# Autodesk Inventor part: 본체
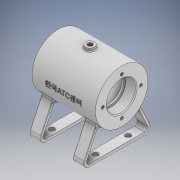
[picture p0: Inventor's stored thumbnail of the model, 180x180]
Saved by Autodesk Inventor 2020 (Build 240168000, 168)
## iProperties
Created: 2021-12
Part Number: 본체
Material: 일반
Document SubType Name: Modeling
Designer: Windows7
Density: 1 g/cm^3
Appearance: 기본값
Mass: 114.909 g
Surface Area: 355.108 cm^2
Volume: 114.909 cm^3
Author: Windows7
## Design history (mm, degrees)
sketch "스케치1"
  geometry: L1 (-35, 29)-(35, 29); L2 (35, 29)-(35, 0); L3 (35, 0)-(-35, 0); L4 (-35, 0)-(-35, 29); L5 (-35, 16)-(-23, 16); L6 (-23, 16)-(-23, 14); L7 (-23, 14)-(-21, 14); L8 (-21, 14)-(-21, 21); L9 (-21, 21)-(21, 21); L10 (21, 21)-(21, 16); L11 (23, 16)-(23, 16); L12 (23, 16)-(35, 16); L13 (21, 16)-(21, 14); L14 (21, 14)-(23, 14); L15 (23, 14)-(23, 16); 2 further points
  constraints: 30 end point, 10 perpendicular, 4 point on line, 2 collinear, 2 midpoint, 2 parallel, 1 horizontal, 1 vertical, 1 vertical alignment
  dimensions: "d0" = 58 diameter of L1 L3; "d1" = 70 distance of L1.start L1.end; "d2" = 12 distance of L5.start L5.end; "d3" = 12 distance of L11.end L12.end; "d4" = 42 distance of L8.end L9.end; "d5" = 32 diameter of L5 L3; "d6" = 28 diameter of L6.end L3; "d7" = 42 diameter of L9 L3; "d8" = 32 diameter of L12 L3
revolve "회전1" sketch "스케치1" stored, may be unused: angle "d9" = 90 deg
node "작업 평면1"
sketch "스케치2"
  geometry: L1 (-22.743, -17.993)-(-40, -55); L2 (-40, -55)-(0, -55); L3 (0, -55)-(0, -29); L4 (-20.574, -20.438)-(-35.291, -52); L5 (-35.291, -52)-(0, -52); L6 (0, -55)-(0, -52); C1 r 16 at (0, 0) reference; A1 r 29 centre (0, 0) between (-22.743, -17.993) and (0, -29) reference; 1 further point
  constraints: 12 end point, 3 point on circle, 1 collinear, 1 horizontal, 1 perpendicular, 1 point on line, 1 vertical alignment
  dimensions: "d11" = 65 deg angle of L2 L1; "d12" = 3 distance between parallel lines of L1 L4; "d14" = 3 distance between parallel lines of L2 L5; "d15" = 40 distance of L1.end L2.end; "d16" = 55 distance from line of L2 point (0, 0)
extrude "돌출1" join sketch "스케치2" distance "d17" = 12; taper "d18" = 0 deg
fillet "모깎기1" dims "d19" = 6
node "작업 평면2"
sketch "스케치3"
  geometry: C1 r 5 at (0, 0); 1 further point
  constraints: 1 centre point, 1 coincident
  dimensions: "d21" = 10 diameter of C1
extrude "돌출2" join sketch "스케치3" stored distance "d22" = 12; taper "d23" = 0 deg
sketch "스케치5"
  geometry: C1 r 5 at (0, 0) reference; C2 r 5 at (0, 0); 2 further points
  constraints: 2 coincident, 1 centre point
  dimensions: "d70" = 10 diameter of C2
hole "구멍1" sketch "스케치5" at (0, 0) diameter "d24" = 5.1881; stored, may be unused: countersink angle "d28" = 90 deg, drill point angle "d30" = 118 deg; dims "d25" = 6, "d26" = 6, "d27" = 6, "d29" = 8
node "작업 평면3"
sketch "스케치6"
  geometry: L1 (-20.739, 3.002)-(20.739, 3.002); L2 (20.739, 3.002)-(20.739, -3.002); L3 (20.739, -3.002)-(-20.739, -3.002); L4 (-20.739, -3.002)-(-20.739, 3.002); L5 (20.739, -3.002)-(-20.739, 3.002); L6 (20.739, 3.002)-(-20.739, -3.002); L7 (-35, -29)-(-35, 29) reference; L8 (-35, 29)-(35, 29) reference; 2 further points
  constraints: 4 end point, 1 midpoint, 2 other
  dimensions: "d32" = 35 distance from line of L7 point (0, 0); "d33" = 29 distance from line of point (0, 0) L8
feature "엠보싱1" sketch "스케치6" dims "d0" = 58, "d1" = 70, "d2" = 12, "d3" = 12, "d4" = 42, "d5" = 32, "d6" = 28, "d7" = 42, "d8" = 32, "d11" = 65 deg, "d12" = 3, "d14" = 3, "d15" = 40, "d16" = 55, "d34" = 0.5, "d35" = 0
sketch "스케치7"
  geometry: L1 (-42, 17.291)-(6, 17.291); L2 (6, 17.291)-(6, 53.291); L3 (6, 53.291)-(-42, 53.291); L4 (-42, 53.291)-(-42, 17.291); L5 (-48, 4.709)-(-48, 65.873) reference; 6 further points
  constraints: 8 end point, 4 coincident, 2 parallel, 1 horizontal, 1 horizontal alignment, 1 midpoint, 1 perpendicular
  dimensions: "d36" = 48 distance of L2.end L3.end; "d37" = 6 distance between parallel lines of L5 L4; "d38" = 36 distance between parallel lines of L1 L3
hole "구멍2" sketch "스케치7" at (-42, 53.291), (6, 53.291), (6, 17.291), (-42, 17.291) diameter "d39" = 6; stored, may be unused: countersink angle "d43" = 90 deg, drill point angle "d45" = 0 deg; dims "d40" = 8, "d41" = 6, "d42" = 6, "d44" = 8.8
sketch "스케치8" dims "d46" = 42
  geometry: L1 (0, 0)-(0, 43.275); 2 further points
  constraints: 2 end point, 1 coincident, 1 point on line, 1 vertical, 1 vertical alignment, 2 other
hole "구멍3" sketch "스케치8" at (0, 21) diameter "d47" = 3.242; stored, may be unused: countersink angle "d51" = 90 deg, drill point angle "d53" = 118 deg; dims "d48" = 8, "d49" = 6, "d50" = 6, "d52" = 10
sketch "스케치9"
  geometry: L1 (0, 0)-(-43.535, 0); L2 (0, 0)-(-30.07, -10.945)
  constraints: 4 end point, 1 horizontal
  dimensions: "d57" = 32 distance of L1.start L2.end; "d58" = 20 deg angle of L2 L1
node "작업 평면4"
sketch "스케치10"
  geometry: C1 r 6 at (0, 0); 2 further points
  constraints: 1 centre point, 1 coincident
  dimensions: "d59" = 12 diameter of C1
extrude "돌출3" join sketch "스케치10" stored distance "d60" = 12; taper "d61" = 0 deg
sketch "스케치11"
  geometry: C1 r 6 at (0, 0) reference; 2 further points
  constraints: 1 coincident
hole "구멍4" sketch "스케치11" at (0, 0) diameter "d62" = 5.1881; stored, may be unused: countersink angle "d66" = 90 deg, drill point angle "d68" = 0 deg; dims "d63" = 12, "d64" = 6, "d65" = 6, "d67" = 16
fillet "모깎기2" dims "d69" = 1
fillet "모깎기3" dims "d71" = 0.3
chamfer "모따기1" distance "d72" = 1; stored, may be unused: second distance "d73" = 2, angle "d74" = 45 deg
fillet "모깎기4" dims "d75" = 3
fillet "모깎기5" dims "d76" = 3
fillet "모깎기6" dims "d77" = 0.5
fillet "모깎기7" dims "d78" = 3
sketch "스케치13"
  geometry: L1 (18, -54.5)-(18, -52.5) reference; L2 (18.5, -52)-(29.5, -52) reference; L3 (30, -52.5)-(30, -54.5) reference; L4 (29.5, -55)-(18.5, -55) reference; L5 (-30, -54.5)-(-30, -52.5) reference; L6 (-29.5, -52)-(-18.5, -52) reference; L7 (-18, -52.5)-(-18, -54.5) reference; L8 (-18.5, -55)-(-29.5, -55) reference; L9 (24.026, -21)-(25, -22.621) reference; L10 (25, -22.621)-(35, -22.621) reference; L11 (35, -22.621)-(35, -29) reference; L12 (35, -29)-(-35, -29) reference; L13 (-35, -29)-(-35, -22.621) reference; L14 (-35, -22.621)-(-25, -22.621) reference; L15 (-25, -22.621)-(-24.026, -21) reference; L16 (-24.026, -21)-(-25, -19.379) reference; L17 (-25, -19.379)-(-35, -19.379) reference; L18 (-35, -19.379)-(-35, -17) reference; L19 (-35, -17)-(-34, -16) reference; L20 (-34, -16)-(-23.3, -16) reference; L21 (-23, -15.7)-(-23, -14) reference; L22 (-23, -14)-(-21, -14) reference; L23 (-21, -14)-(-21, -18) reference; L24 (-18, -21)-(18, -21) reference; L25 (21, -18)-(21, -14) reference; L26 (21, -14)-(23, -14) reference; L27 (23, -14)-(23, -15.7) reference; L28 (23.3, -16)-(34, -16) reference; L29 (34, -16)-(35, -17) reference; L30 (35, -17)-(35, -19.379) reference; L31 (35, -19.379)-(25, -19.379) reference; L32 (25, -19.379)-(24.026, -21) reference; L33 (25, 22.621)-(24.026, 21) reference; L34 (24.026, 21)-(25, 19.379) reference; L35 (25, 19.379)-(35, 19.379) reference; L36 (35, 19.379)-(35, 17) reference; L37 (35, 17)-(34, 16) reference; L38 (34, 16)-(23.3, 16) reference; L39 (23, 15.7)-(23, 14) reference; L40 (23, 14)-(21, 14) reference; L41 (21, 14)-(21, 18) reference; L42 (18, 21)-(-18, 21) reference; L43 (-21, 18)-(-21, 14) reference; L44 (-21, 14)-(-23, 14) reference; L45 (-23, 14)-(-23, 15.7) reference; L46 (-23.3, 16)-(-34, 16) reference; L47 (-34, 16)-(-35, 17) reference; L48 (-35, 17)-(-35, 19.379) reference; L49 (-35, 19.379)-(-25, 19.379) reference; L50 (-25, 19.379)-(-24.026, 21) reference; L51 (-24.026, 21)-(-25, 22.621) reference; L52 (-25, 22.621)-(-35, 22.621) reference; L53 (-35, 22.621)-(-35, 29) reference; L54 (-35, 29)-(-6, 29) reference; L55 (-5, 30)-(-5, 32) reference; L56 (-5, 32)-(-2.594, 32) reference; L57 (-2.594, 32)-(-2.594, 24) reference; L58 (-2.594, 24)-(0, 22.441) reference; L59 (0, 22.441)-(2.594, 24) reference; L60 (2.594, 24)-(2.594, 32) reference; L61 (2.594, 32)-(5, 32) reference; L62 (5, 32)-(5, 30) reference; L63 (6, 29)-(35, 29) reference; L64 (35, 29)-(35, 22.621) reference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; A1 r 0.5 centre (18.5, -52.5) between (18.5, -52) and (18, -52.5) reference; A2 r 0.5 centre (29.5, -52.5) between (30, -52.5) and (29.5, -52) reference; A3 r 0.5 centre (29.5, -54.5) between (29.5, -55) and (30, -54.5) reference; A4 r 0.5 centre (18.5, -54.5) between (18, -54.5) and (18.5, -55) reference; A5 r 0.5 centre (-29.5, -52.5) between (-29.5, -52) and (-30, -52.5) reference; A6 r 0.5 centre (-18.5, -52.5) between (-18, -52.5) and (-18.5, -52) reference; A7 r 0.5 centre (-18.5, -54.5) between (-18.5, -55) and (-18, -54.5) reference; A8 r 0.5 centre (-29.5, -54.5) between (-30, -54.5) and (-29.5, -55) reference; A9 r 0.3 centre (-23.3, -15.7) between (-23.3, -16) and (-23, -15.7) reference; A10 r 3 centre (-18, -18) between (-21, -18) and (-18, -21) reference; A11 r 3 centre (18, -18) between (18, -21) and (21, -18) reference; A12 r 0.3 centre (23.3, -15.7) between (23, -15.7) and (23.3, -16) reference; A13 r 0.3 centre (23.3, 15.7) between (23.3, 16) and (23, 15.7) reference; A14 r 3 centre (18, 18) between (21, 18) and (18, 21) reference; A15 r 3 centre (-18, 18) between (-18, 21) and (-21, 18) reference; A16 r 0.3 centre (-23.3, 15.7) between (-23, 15.7) and (-23.3, 16) reference; 2 further points
  constraints: 8 end point, 2 parallel, 1 horizontal, 1 midpoint, 1 perpendicular, 1 point on line, 2 other
  dimensions: "d79" = 1.5 distance of L67.end L68.end
revolve "회전2" sketch "스케치13" stored, may be unused: angle "d80" = 90 deg
fillet "모깎기8" dims "d81" = 1
node "솔리드1"
mirror "미러1"
mirror "미러2"
pattern_circular "원형 패턴1" dims angle "d55" = 360 deg
mirror "미러3"
node "절단 모서리 투영1"
node "절단 모서리 투영2"
feature "A9D066F2-1C7D-4E18-AEED-F7BC21143FA4" dims "d39" = 6, "d40" = 8, "d41" = 6, "d42" = 6, "d43" = 90 deg, "d44" = 8.8, "d45" = 0
other parameters: "d10" = -5, "d20" = 32, "d31" = 47
